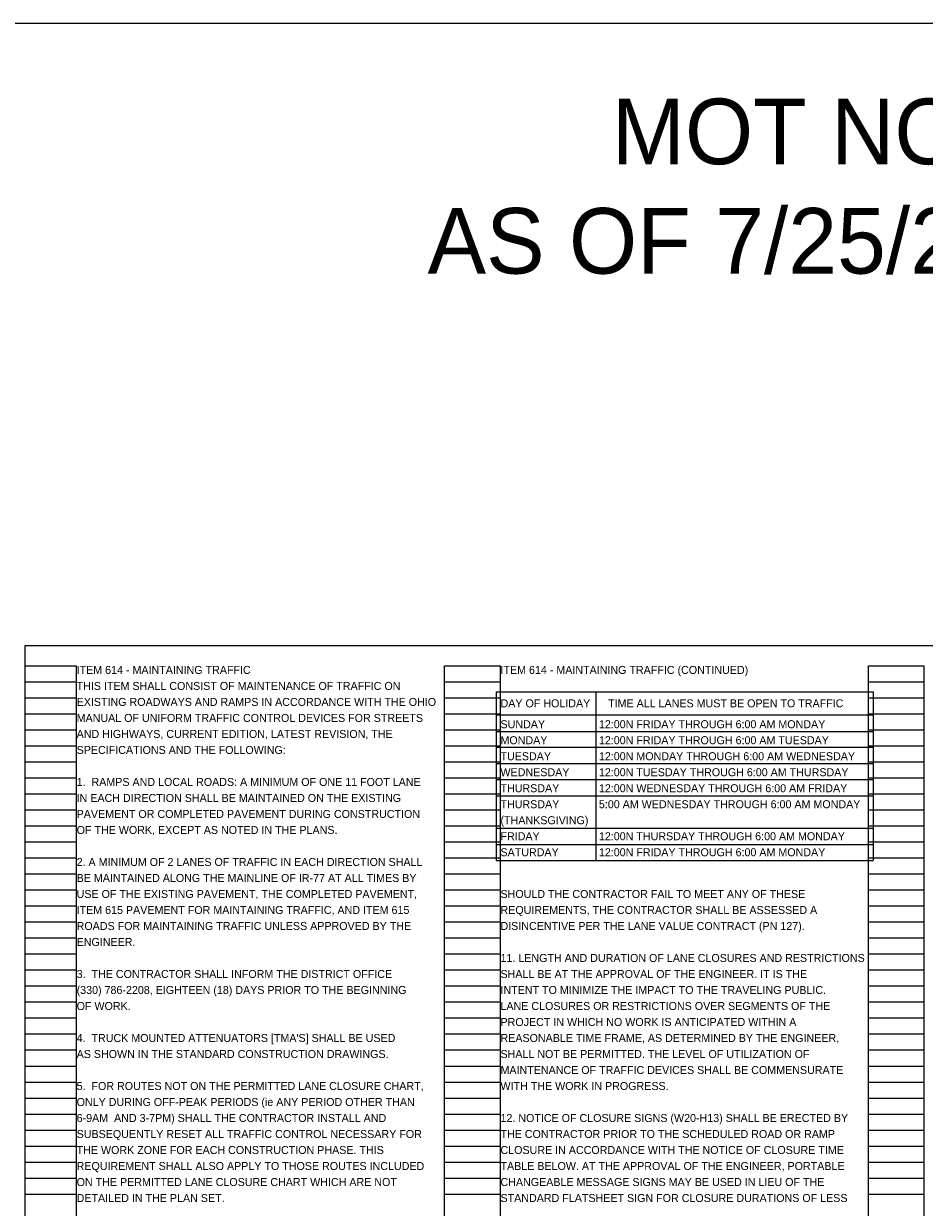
# Model space of a CAD drawing. Extents: x 1820207 to 1820557, y 740216 to 740315.
# Drawn here: x 1820225.52 to 1820241.29, y 740265.91 to 740286.62 of the extents above; entities that cross this region are included whole.
import ezdxf

# ---------------------------------------------------------------- set-up
doc = ezdxf.new("R2010")
doc.units = 0
for name, color, linetype in [('SC_Scratch1', 7, 'Continuous'), ('SC_Scratch2', 7, 'Continuous'), ('SH_Text', 7, 'Continuous')]:
    doc.layers.add(name, color=color, linetype=linetype)

msp = doc.modelspace()

# ---------------------------------------------------------------- linework, layer by layer
at = {"layer": 'SC_Scratch1'}
for p, q in [((1820225.547, 740255.222), (1820225.547, 740275.382)), ((1820225.547, 740275.382), (1820226.447, 740275.382)), ((1820226.447, 740255.222), (1820226.447, 740275.382)), ((1820232.887, 740255.222), (1820232.887, 740275.382)), ((1820232.887, 740275.382), (1820233.867, 740275.382)), ((1820233.867, 740255.222), (1820233.867, 740275.382)), ((1820240.307, 740255.222), (1820240.307, 740275.382)), ((1820240.307, 740275.382), (1820241.287, 740275.382)), ((1820241.287, 740255.222), (1820241.287, 740275.382)), ((1820225.547, 740275.102), (1820226.447, 740275.102)), ((1820232.887, 740275.102), (1820233.867, 740275.102)), ((1820240.307, 740275.102), (1820241.287, 740275.102)), ((1820225.547, 740274.822), (1820226.447, 740274.822)), ((1820232.887, 740274.822), (1820233.867, 740274.822)), ((1820240.307, 740274.822), (1820241.287, 740274.822)), ((1820225.547, 740274.542), (1820226.447, 740274.542)), ((1820232.887, 740274.542), (1820233.867, 740274.542)), ((1820240.307, 740274.542), (1820241.287, 740274.542)), ((1820225.547, 740274.262), (1820226.447, 740274.262)), ((1820232.887, 740274.262), (1820233.867, 740274.262)), ((1820240.307, 740274.262), (1820241.287, 740274.262)), ((1820225.547, 740273.982), (1820226.447, 740273.982)), ((1820232.887, 740273.982), (1820233.867, 740273.982)), ((1820240.307, 740273.982), (1820241.287, 740273.982)), ((1820225.547, 740273.702), (1820226.447, 740273.702)), ((1820232.887, 740273.702), (1820233.867, 740273.702)), ((1820240.307, 740273.702), (1820241.287, 740273.702)), ((1820225.547, 740273.422), (1820226.447, 740273.422)), ((1820232.887, 740273.422), (1820233.867, 740273.422)), ((1820240.307, 740273.422), (1820241.287, 740273.422)), ((1820225.547, 740273.142), (1820226.447, 740273.142)), ((1820232.887, 740273.142), (1820233.867, 740273.142)), ((1820240.307, 740273.142), (1820241.287, 740273.142)), ((1820225.547, 740272.862), (1820226.447, 740272.862)), ((1820232.887, 740272.862), (1820233.867, 740272.862)), ((1820240.307, 740272.862), (1820241.287, 740272.862)), ((1820225.547, 740272.582), (1820226.447, 740272.582)), ((1820232.887, 740272.582), (1820233.867, 740272.582)), ((1820240.307, 740272.582), (1820241.287, 740272.582)), ((1820225.547, 740272.302), (1820226.447, 740272.302)), ((1820232.887, 740272.302), (1820233.867, 740272.302)), ((1820240.307, 740272.302), (1820241.287, 740272.302)), ((1820225.547, 740272.022), (1820226.447, 740272.022)), ((1820232.887, 740272.022), (1820233.867, 740272.022)), ((1820240.307, 740272.022), (1820241.287, 740272.022)), ((1820225.547, 740271.742), (1820226.447, 740271.742)), ((1820232.887, 740271.742), (1820233.867, 740271.742)), ((1820240.307, 740271.742), (1820241.287, 740271.742)), ((1820225.547, 740271.462), (1820226.447, 740271.462)), ((1820232.887, 740271.462), (1820233.867, 740271.462)), ((1820240.307, 740271.462), (1820241.287, 740271.462)), ((1820225.547, 740271.182), (1820226.447, 740271.182)), ((1820232.887, 740271.182), (1820233.867, 740271.182)), ((1820240.307, 740271.182), (1820241.287, 740271.182)), ((1820225.547, 740270.902), (1820226.447, 740270.902)), ((1820232.887, 740270.902), (1820233.867, 740270.902)), ((1820240.307, 740270.902), (1820241.287, 740270.902)), ((1820225.547, 740270.622), (1820226.447, 740270.622)), ((1820232.887, 740270.622), (1820233.867, 740270.622)), ((1820240.307, 740270.622), (1820241.287, 740270.622)), ((1820225.547, 740270.342), (1820226.447, 740270.342)), ((1820232.887, 740270.342), (1820233.867, 740270.342)), ((1820240.307, 740270.342), (1820241.287, 740270.342)), ((1820225.547, 740270.062), (1820226.447, 740270.062)), ((1820232.887, 740270.062), (1820233.867, 740270.062)), ((1820240.307, 740270.062), (1820241.287, 740270.062)), ((1820225.547, 740269.782), (1820226.447, 740269.782)), ((1820232.887, 740269.782), (1820233.867, 740269.782)), ((1820240.307, 740269.782), (1820241.287, 740269.782)), ((1820225.547, 740269.502), (1820226.447, 740269.502)), ((1820232.887, 740269.502), (1820233.867, 740269.502)), ((1820240.307, 740269.502), (1820241.287, 740269.502)), ((1820225.547, 740269.222), (1820226.447, 740269.222)), ((1820232.887, 740269.222), (1820233.867, 740269.222)), ((1820240.307, 740269.222), (1820241.287, 740269.222)), ((1820225.547, 740268.942), (1820226.447, 740268.942)), ((1820232.887, 740268.942), (1820233.867, 740268.942)), ((1820240.307, 740268.942), (1820241.287, 740268.942)), ((1820225.547, 740268.662), (1820226.447, 740268.662)), ((1820232.887, 740268.662), (1820233.867, 740268.662)), ((1820240.307, 740268.662), (1820241.287, 740268.662)), ((1820225.547, 740268.382), (1820226.447, 740268.382)), ((1820232.887, 740268.382), (1820233.867, 740268.382)), ((1820240.307, 740268.382), (1820241.287, 740268.382)), ((1820225.547, 740268.102), (1820226.447, 740268.102)), ((1820232.887, 740268.102), (1820233.867, 740268.102)), ((1820240.307, 740268.102), (1820241.287, 740268.102)), ((1820225.547, 740267.822), (1820226.447, 740267.822)), ((1820232.887, 740267.822), (1820233.867, 740267.822)), ((1820240.307, 740267.822), (1820241.287, 740267.822)), ((1820225.547, 740267.542), (1820226.447, 740267.542)), ((1820232.887, 740267.542), (1820233.867, 740267.542)), ((1820240.307, 740267.542), (1820241.287, 740267.542)), ((1820225.547, 740267.262), (1820226.447, 740267.262)), ((1820232.887, 740267.262), (1820233.867, 740267.262)), ((1820240.307, 740267.262), (1820241.287, 740267.262)), ((1820225.547, 740266.982), (1820226.447, 740266.982)), ((1820232.887, 740266.982), (1820233.867, 740266.982)), ((1820240.307, 740266.982), (1820241.287, 740266.982)), ((1820225.547, 740266.702), (1820226.447, 740266.702)), ((1820232.887, 740266.702), (1820233.867, 740266.702)), ((1820240.307, 740266.702), (1820241.287, 740266.702)), ((1820225.547, 740266.422), (1820226.447, 740266.422)), ((1820232.887, 740266.422), (1820233.867, 740266.422)), ((1820240.307, 740266.422), (1820241.287, 740266.422)), ((1820225.547, 740266.142), (1820226.447, 740266.142)), ((1820232.887, 740266.142), (1820233.867, 740266.142)), ((1820240.307, 740266.142), (1820241.287, 740266.142))]:
    msp.add_line(p, q, dxfattribs=at)
at = {"layer": 'SC_Scratch2'}
msp.add_lwpolyline([(1820225.547, 740275.742), (1820256.047, 740275.742), (1820256.047, 740254.742), (1820225.547, 740254.742)], close=True, dxfattribs=at)
at = {"layer": 'SH_Text'}
for p, q in [((1820233.791, 740274.929), (1820233.791, 740271.976)), ((1820233.791, 740274.929), (1820240.394, 740274.929)), ((1820235.537, 740274.929), (1820235.537, 740271.976)), ((1820240.394, 740274.929), (1820240.394, 740271.976)), ((1820233.791, 740274.527), (1820240.394, 740274.527)), ((1820233.791, 740274.235), (1820240.394, 740274.235)), ((1820233.791, 740273.96), (1820240.394, 740273.96)), ((1820233.791, 740273.677), (1820240.394, 740273.677)), ((1820233.791, 740273.393), (1820240.394, 740273.393)), ((1820233.791, 740273.11), (1820240.394, 740273.11)), ((1820233.791, 740272.543), (1820240.394, 740272.543)), ((1820233.791, 740272.259), (1820240.394, 740272.259)), ((1820233.791, 740271.976), (1820240.394, 740271.976))]:
    msp.add_line(p, q, dxfattribs=at)
msp.add_lwpolyline([(1820217.201, 740244.009), (1820515.724, 740244.009), (1820515.724, 740286.62), (1820217.201, 740286.62)], close=True, dxfattribs=at)

# ---------------------------------------------------------------- texts
at = {"layer": 'SC_Scratch2'}
for s, height, p in [('MOT NOTES', 1.1483, (1820235.817, 740284.16)), ('AS OF 7/25/2023', 1.14829, (1820232.591, 740282.246))]:
    msp.add_text(s, height=height, rotation=360, dxfattribs=at).set_placement(p)
at = {"layer": 'SH_Text'}
for s, p in [('ITEM 614 - MAINTAINING TRAFFIC', (1820226.447, 740275.242)), ('ITEM 614 - MAINTAINING TRAFFIC (CONTINUED)', (1820233.867, 740275.242)), ('THIS ITEM SHALL CONSIST OF MAINTENANCE OF TRAFFIC ON', (1820226.447, 740274.962)), ('EXISTING ROADWAYS AND RAMPS IN ACCORDANCE WITH THE OHIO', (1820226.447, 740274.682)), ('DAY OF HOLIDAY', (1820233.868, 740274.658)), ('TIME ALL LANES MUST BE OPEN TO TRAFFIC', (1820235.751, 740274.658)), ('MANUAL OF UNIFORM TRAFFIC CONTROL DEVICES FOR STREETS ', (1820226.447, 740274.402)), ('SUNDAY', (1820233.867, 740274.292)), ('12:00N FRIDAY THROUGH 6:00 AM MONDAY', (1820235.59, 740274.292)), ('AND HIGHWAYS, CURRENT EDITION, LATEST REVISION, THE ', (1820226.447, 740274.122)), ('MONDAY', (1820233.867, 740274.012)), ('12:00N FRIDAY THROUGH 6:00 AM TUESDAY', (1820235.59, 740274.012)), ('SPECIFICATIONS AND THE FOLLOWING:', (1820226.447, 740273.842)), ('TUESDAY', (1820233.867, 740273.732)), ('12:00N MONDAY THROUGH 6:00 AM WEDNESDAY', (1820235.59, 740273.732)), ('WEDNESDAY', (1820233.867, 740273.452)), ('12:00N TUESDAY THROUGH 6:00 AM THURSDAY', (1820235.59, 740273.452)), ('1.  RAMPS AND LOCAL ROADS: A MINIMUM OF ONE 11 FOOT LANE ', (1820226.447, 740273.282)), ('THURSDAY', (1820233.867, 740273.172)), ('12:00N WEDNESDAY THROUGH 6:00 AM FRIDAY', (1820235.59, 740273.172)), ('IN EACH DIRECTION SHALL BE MAINTAINED ON THE EXISTING ', (1820226.447, 740273.002)), ('THURSDAY', (1820233.867, 740272.892)), ('5:00 AM WEDNESDAY THROUGH 6:00 AM MONDAY', (1820235.59, 740272.892)), ('PAVEMENT OR COMPLETED PAVEMENT DURING CONSTRUCTION ', (1820226.447, 740272.722)), ('(THANKSGIVING)', (1820233.867, 740272.612)), ('OF THE WORK, EXCEPT AS NOTED IN THE PLANS.', (1820226.447, 740272.442)), ('FRIDAY', (1820233.867, 740272.332)), ('12:00N THURSDAY THROUGH 6:00 AM MONDAY', (1820235.59, 740272.332)), ('SATURDAY', (1820233.867, 740272.052)), ('12:00N FRIDAY THROUGH 6:00 AM MONDAY', (1820235.59, 740272.052)), ('2. A MINIMUM OF 2 LANES OF TRAFFIC IN EACH DIRECTION SHALL ', (1820226.447, 740271.882)), ('BE MAINTAINED ALONG THE MAINLINE OF IR-77 AT ALL TIMES BY ', (1820226.447, 740271.602)), ('USE OF THE EXISTING PAVEMENT, THE COMPLETED PAVEMENT, ', (1820226.447, 740271.322)), ('SHOULD THE CONTRACTOR FAIL TO MEET ANY OF THESE ', (1820233.867, 740271.322)), ('ITEM 615 PAVEMENT FOR MAINTAINING TRAFFIC, AND ITEM 615 ', (1820226.447, 740271.042)), ('REQUIREMENTS, THE CONTRACTOR SHALL BE ASSESSED A ', (1820233.867, 740271.042)), ('ROADS FOR MAINTAINING TRAFFIC UNLESS APPROVED BY THE ', (1820226.447, 740270.762)), ('DISINCENTIVE PER THE LANE VALUE CONTRACT (PN 127).', (1820233.867, 740270.762)), ('ENGINEER.', (1820226.447, 740270.482)), ('11. LENGTH AND DURATION OF LANE CLOSURES AND RESTRICTIONS ', (1820233.867, 740270.202)), ('3.  THE CONTRACTOR SHALL INFORM THE DISTRICT OFFICE', (1820226.447, 740269.922)), ('SHALL BE AT THE APPROVAL OF THE ENGINEER. IT IS THE ', (1820233.867, 740269.922)), ('(330) 786-2208, EIGHTEEN (18) DAYS PRIOR TO THE BEGINNING', (1820226.447, 740269.642)), ('INTENT TO MINIMIZE THE IMPACT TO THE TRAVELING PUBLIC. ', (1820233.867, 740269.642)), ('OF WORK.', (1820226.447, 740269.362)), ('LANE CLOSURES OR RESTRICTIONS OVER SEGMENTS OF THE ', (1820233.867, 740269.362)), ('PROJECT IN WHICH NO WORK IS ANTICIPATED WITHIN A ', (1820233.867, 740269.082)), ("4.  TRUCK MOUNTED ATTENUATORS [TMA'S] SHALL BE USED", (1820226.447, 740268.802)), ('REASONABLE TIME FRAME, AS DETERMINED BY THE ENGINEER, ', (1820233.867, 740268.802)), ('AS SHOWN IN THE STANDARD CONSTRUCTION DRAWINGS.', (1820226.447, 740268.522)), ('SHALL NOT BE PERMITTED. THE LEVEL OF UTILIZATION OF ', (1820233.867, 740268.522)), ('MAINTENANCE OF TRAFFIC DEVICES SHALL BE COMMENSURATE ', (1820233.867, 740268.242)), ('5.  FOR ROUTES NOT ON THE PERMITTED LANE CLOSURE CHART,', (1820226.447, 740267.962)), ('WITH THE WORK IN PROGRESS.', (1820233.867, 740267.962)), ('ONLY DURING OFF-PEAK PERIODS (ie ANY PERIOD OTHER THAN ', (1820226.447, 740267.682)), ('6-9AM  AND 3-7PM) SHALL THE CONTRACTOR INSTALL AND ', (1820226.447, 740267.402)), ('12. NOTICE OF CLOSURE SIGNS (W20-H13) SHALL BE ERECTED BY ', (1820233.867, 740267.402)), ('SUBSEQUENTLY RESET ALL TRAFFIC CONTROL NECESSARY FOR ', (1820226.447, 740267.122)), ('THE CONTRACTOR PRIOR TO THE SCHEDULED ROAD OR RAMP ', (1820233.867, 740267.122)), ('THE WORK ZONE FOR EACH CONSTRUCTION PHASE. THIS ', (1820226.447, 740266.842)), ('CLOSURE IN ACCORDANCE WITH THE NOTICE OF CLOSURE TIME ', (1820233.867, 740266.842)), ('REQUIREMENT SHALL ALSO APPLY TO THOSE ROUTES INCLUDED ', (1820226.447, 740266.562)), ('TABLE BELOW. AT THE APPROVAL OF THE ENGINEER, PORTABLE ', (1820233.867, 740266.562)), ('ON THE PERMITTED LANE CLOSURE CHART WHICH ARE NOT ', (1820226.447, 740266.282)), ('CHANGEABLE MESSAGE SIGNS MAY BE USED IN LIEU OF THE ', (1820233.867, 740266.282)), ('DETAILED IN THE PLAN SET.', (1820226.447, 740266.002)), ('STANDARD FLATSHEET SIGN FOR CLOSURE DURATIONS OF LESS ', (1820233.867, 740266.002))]:
    msp.add_text(s, height=0.14, dxfattribs=at).set_placement(p)

doc.saveas('drawing.dxf')
